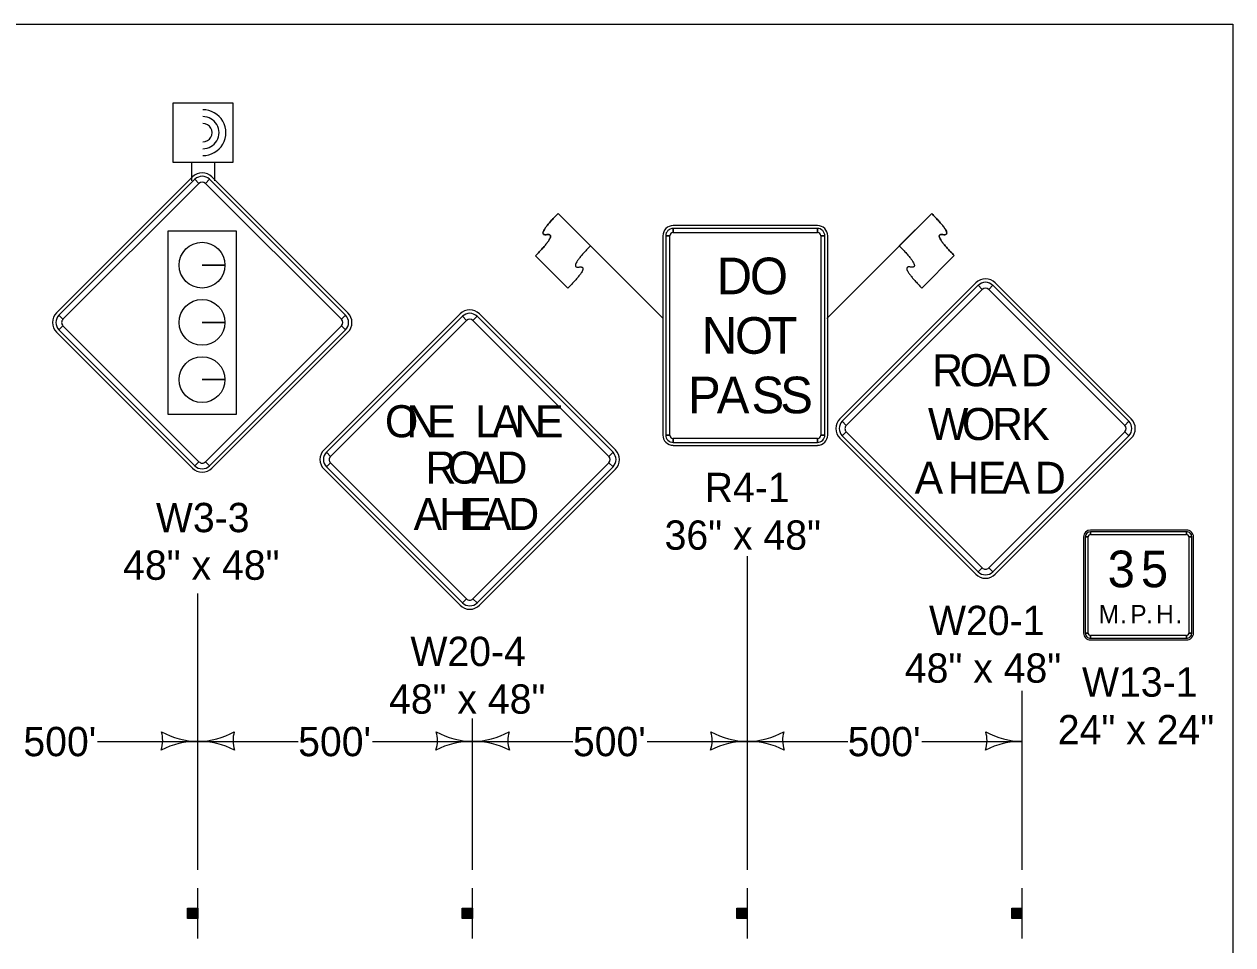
# Model space of a CAD drawing. Extents: x -2134934 to -2127057, y -2139046 to -2137036.
# Drawn here: x -2127757 to -2127097, y -2137539 to -2137036 of the extents above; entities that cross this region are included whole.
import ezdxf

# ---------------------------------------------------------------- set-up
doc = ezdxf.new("R2010")
doc.units = 0
for name, color, linetype in [('Barrier', 7, 'Continuous'), ('BridgeSuperStructureExisting', 7, 'Continuous'), ('Default', 7, 'Continuous'), ('TC_Barrier', 7, 'Continuous')]:
    doc.layers.add(name, color=color, linetype=linetype)

msp = doc.modelspace()

# ---------------------------------------------------------------- linework, layer by layer
at = {"layer": 'Barrier'}
for p, q in [((-2127664.88, -2137119.33), (-2127739.13, -2137193.57)), ((-2127663.56, -2137120.65), (-2127661.35, -2137122.86)), ((-2127657.81, -2137122.86), (-2127655.6, -2137120.65)), ((-2127580.03, -2137193.57), (-2127654.28, -2137119.33)), ((-2127407.97, -2137196.68), (-2127465.31, -2137139.38)), ((-2127465.31, -2137139.38), (-2127447.62, -2137157.06)), ((-2127318.68, -2137196.68), (-2127261.36, -2137139.36)), ((-2127261.36, -2137139.36), (-2127279.05, -2137157.04)), ((-2127323.73, -2137145.92), (-2127402.48, -2137145.92)), ((-2127402.48, -2137149.67), (-2127402.48, -2137147.48)), ((-2127323.73, -2137147.48), (-2127323.73, -2137149.67)), ((-2127408.11, -2137151.54), (-2127408.11, -2137260.29)), ((-2127406.54, -2137151.54), (-2127404.36, -2137151.54)), ((-2127321.86, -2137151.54), (-2127319.67, -2137151.54)), ((-2127318.11, -2137260.29), (-2127318.11, -2137151.54)), ((-2127460, -2137180.05), (-2127477.68, -2137162.37)), ((-2127266.66, -2137180.03), (-2127248.99, -2137162.35)), ((-2127647.17, -2137167.55), (-2127659.67, -2137167.55)), ((-2127659.67, -2137167.55), (-2127647.17, -2137167.55)), ((-2127237.26, -2137177.23), (-2127311.51, -2137251.47)), ((-2127152.41, -2137251.47), (-2127226.65, -2137177.23)), ((-2127235.93, -2137178.55), (-2127233.72, -2137180.76)), ((-2127230.19, -2137180.76), (-2127227.98, -2137178.55)), ((-2127735.59, -2137197.11), (-2127737.8, -2137194.9)), ((-2127518.85, -2137194.14), (-2127593.09, -2137268.39)), ((-2127581.36, -2137194.9), (-2127583.56, -2137197.11)), ((-2127517.52, -2137195.47), (-2127515.31, -2137197.68)), ((-2127511.78, -2137197.68), (-2127509.57, -2137195.47)), ((-2127433.99, -2137268.39), (-2127508.24, -2137194.14)), ((-2127739.13, -2137204.18), (-2127664.88, -2137278.43)), ((-2127737.8, -2137202.85), (-2127735.59, -2137200.64)), ((-2127647.17, -2137198.8), (-2127659.67, -2137198.8)), ((-2127659.67, -2137198.8), (-2127647.17, -2137198.8)), ((-2127654.28, -2137278.43), (-2127580.03, -2137204.18)), ((-2127583.56, -2137200.64), (-2127581.36, -2137202.85)), ((-2127647.17, -2137230.05), (-2127659.67, -2137230.05)), ((-2127659.67, -2137230.05), (-2127647.17, -2137230.05)), ((-2127307.97, -2137255.01), (-2127310.18, -2137252.8)), ((-2127153.73, -2137252.8), (-2127155.94, -2137255.01)), ((-2127404.36, -2137260.29), (-2127406.54, -2137260.29)), ((-2127402.48, -2137264.35), (-2127402.48, -2137262.17)), ((-2127323.73, -2137262.17), (-2127323.73, -2137264.35)), ((-2127319.67, -2137260.29), (-2127321.86, -2137260.29)), ((-2127311.51, -2137262.08), (-2127237.26, -2137336.33)), ((-2127310.18, -2137260.75), (-2127307.97, -2137258.54)), ((-2127226.65, -2137336.33), (-2127152.41, -2137262.08)), ((-2127155.94, -2137258.54), (-2127153.73, -2137260.75)), ((-2127589.56, -2137271.93), (-2127591.77, -2137269.72)), ((-2127435.32, -2137269.72), (-2127437.53, -2137271.93)), ((-2127402.48, -2137265.92), (-2127323.73, -2137265.92)), ((-2127661.35, -2137274.89), (-2127663.56, -2137277.1)), ((-2127655.6, -2137277.1), (-2127657.81, -2137274.89)), ((-2127591.77, -2137277.67), (-2127589.56, -2137275.46)), ((-2127437.53, -2137275.46), (-2127435.32, -2137277.67)), ((-2127593.09, -2137279), (-2127518.85, -2137353.24)), ((-2127508.24, -2137353.24), (-2127433.99, -2137279)), ((-2127178.44, -2137315.92), (-2127178.44, -2137368.42)), ((-2127177.5, -2137315.92), (-2127175.94, -2137315.92)), ((-2127122.19, -2137312.17), (-2127174.69, -2137312.17)), ((-2127174.69, -2137314.67), (-2127174.69, -2137313.1)), ((-2127122.19, -2137313.1), (-2127122.19, -2137314.67)), ((-2127120.94, -2137315.92), (-2127119.37, -2137315.92)), ((-2127118.44, -2137368.42), (-2127118.44, -2137315.92)), ((-2127233.72, -2137332.79), (-2127235.93, -2137335)), ((-2127227.98, -2137335), (-2127230.19, -2137332.79)), ((-2127515.31, -2137349.71), (-2127517.52, -2137351.92)), ((-2127509.57, -2137351.92), (-2127511.78, -2137349.71)), ((-2127175.94, -2137368.42), (-2127177.5, -2137368.42)), ((-2127119.37, -2137368.42), (-2127120.94, -2137368.42)), ((-2127174.69, -2137371.23), (-2127174.69, -2137369.67)), ((-2127174.69, -2137372.17), (-2127122.19, -2137372.17)), ((-2127122.19, -2137369.67), (-2127122.19, -2137371.23))]:
    msp.add_line(p, q, dxfattribs=at)
for points in [[(-2127663.56, -2137120.65), (-2127737.8, -2137194.9), (-2127735.59, -2137197.11), (-2127661.35, -2137122.86), (-2127663.56, -2137120.65)], [(-2127581.36, -2137194.9), (-2127655.6, -2137120.65), (-2127657.81, -2137122.86), (-2127583.56, -2137197.11), (-2127581.36, -2137194.9)], [(-2127640.85, -2137148.93), (-2127678.31, -2137148.93), (-2127678.31, -2137248.82), (-2127640.85, -2137248.82), (-2127640.85, -2137148.93)], [(-2127323.73, -2137147.48), (-2127402.48, -2137147.48), (-2127402.48, -2137149.67), (-2127323.73, -2137149.67), (-2127323.73, -2137147.48)], [(-2127406.54, -2137151.54), (-2127406.54, -2137260.29), (-2127404.36, -2137260.29), (-2127404.36, -2137151.54), (-2127406.54, -2137151.54)], [(-2127319.67, -2137260.29), (-2127319.67, -2137151.54), (-2127321.86, -2137151.54), (-2127321.86, -2137260.29), (-2127319.67, -2137260.29)], [(-2127235.93, -2137178.55), (-2127310.18, -2137252.8), (-2127307.97, -2137255.01), (-2127233.72, -2137180.76), (-2127235.93, -2137178.55)], [(-2127153.73, -2137252.8), (-2127227.98, -2137178.55), (-2127230.19, -2137180.76), (-2127155.94, -2137255.01), (-2127153.73, -2137252.8)], [(-2127517.52, -2137195.47), (-2127591.77, -2137269.72), (-2127589.56, -2137271.93), (-2127515.31, -2137197.68), (-2127517.52, -2137195.47)], [(-2127435.32, -2137269.72), (-2127509.57, -2137195.47), (-2127511.78, -2137197.68), (-2127437.53, -2137271.93), (-2127435.32, -2137269.72)], [(-2127737.8, -2137202.85), (-2127663.56, -2137277.1), (-2127661.35, -2137274.89), (-2127735.59, -2137200.64), (-2127737.8, -2137202.85)], [(-2127655.6, -2137277.1), (-2127581.36, -2137202.85), (-2127583.56, -2137200.64), (-2127657.81, -2137274.89), (-2127655.6, -2137277.1)], [(-2127402.48, -2137264.35), (-2127323.73, -2137264.35), (-2127323.73, -2137262.17), (-2127402.48, -2137262.17), (-2127402.48, -2137264.35)], [(-2127310.18, -2137260.75), (-2127235.93, -2137335), (-2127233.72, -2137332.79), (-2127307.97, -2137258.54), (-2127310.18, -2137260.75)], [(-2127227.98, -2137335), (-2127153.73, -2137260.75), (-2127155.94, -2137258.54), (-2127230.19, -2137332.79), (-2127227.98, -2137335)], [(-2127591.77, -2137277.67), (-2127517.52, -2137351.92), (-2127515.31, -2137349.71), (-2127589.56, -2137275.46), (-2127591.77, -2137277.67)], [(-2127509.57, -2137351.92), (-2127435.32, -2137277.67), (-2127437.53, -2137275.46), (-2127511.78, -2137349.71), (-2127509.57, -2137351.92)], [(-2127177.5, -2137315.92), (-2127177.5, -2137368.42), (-2127175.94, -2137368.42), (-2127175.94, -2137315.92), (-2127177.5, -2137315.92)], [(-2127122.19, -2137313.1), (-2127174.69, -2137313.1), (-2127174.69, -2137314.67), (-2127122.19, -2137314.67), (-2127122.19, -2137313.1)], [(-2127119.37, -2137368.42), (-2127119.37, -2137315.92), (-2127120.94, -2137315.92), (-2127120.94, -2137368.42), (-2127119.37, -2137368.42)], [(-2127174.69, -2137371.23), (-2127122.19, -2137371.23), (-2127122.19, -2137369.67), (-2127174.69, -2137369.67), (-2127174.69, -2137371.23)]]:
    msp.add_lwpolyline(points, close=True, dxfattribs=at)
for centre in [(-2127659.67, -2137167.55), (-2127659.67, -2137198.8), (-2127659.67, -2137230.05)]:
    msp.add_circle(centre, 12.5, dxfattribs=at)
for centre, radius, start, end in [((-2127659.58, -2137124.63), 7.5, 44.99999, 134.99974), ((-2127659.58, -2137124.63), 5.62, 44.99999, 134.99974), ((-2127659.58, -2137124.63), 2.5, 44.99999, 134.99974), ((-2127402.48, -2137151.54), 5.62, 90.00021, 179.99985), ((-2127402.48, -2137151.54), 4.06, 90.00021, 179.99985), ((-2127402.48, -2137151.54), 1.87, 90.00021, 179.99985), ((-2127323.73, -2137151.54), 5.62, 0, 90.00021), ((-2127323.73, -2137151.54), 4.06, 0, 90.00021), ((-2127323.73, -2137151.54), 1.87, 0, 90.00021), ((-2127231.96, -2137182.53), 7.5, 44.99999, 134.99974), ((-2127231.96, -2137182.53), 5.62, 44.99999, 134.99974), ((-2127231.96, -2137182.53), 2.5, 44.99999, 134.99974), ((-2127733.83, -2137198.88), 7.5, 134.99974, 224.99995), ((-2127733.83, -2137198.88), 5.62, 134.99974, 224.99995), ((-2127733.83, -2137198.88), 2.5, 134.99974, 224.99995), ((-2127585.33, -2137198.88), 2.5, 315.00016, 44.9998), ((-2127585.33, -2137198.88), 5.62, 315.00016, 44.9998), ((-2127585.33, -2137198.88), 7.5, 315.00016, 44.9998), ((-2127513.54, -2137199.45), 7.5, 44.99999, 134.99974), ((-2127513.54, -2137199.45), 5.62, 44.99999, 134.99974), ((-2127513.54, -2137199.45), 2.5, 44.99999, 134.99974), ((-2127306.2, -2137256.78), 7.5, 134.99974, 224.99995), ((-2127306.2, -2137256.78), 5.62, 134.99974, 224.99995), ((-2127306.2, -2137256.78), 2.5, 134.99974, 224.99995), ((-2127157.71, -2137256.78), 2.5, 315.00016, 44.9998), ((-2127157.71, -2137256.78), 5.62, 315.00016, 44.9998), ((-2127157.71, -2137256.78), 7.5, 315.00016, 44.9998), ((-2127402.48, -2137260.29), 5.62, 179.99985, 270.00006), ((-2127402.48, -2137260.29), 4.06, 179.99985, 270.00006), ((-2127402.48, -2137260.29), 1.87, 179.99985, 270.00006), ((-2127323.73, -2137260.29), 5.62, 270.00006, 0.00027), ((-2127323.73, -2137260.29), 4.06, 270.00006, 0.00027), ((-2127323.73, -2137260.29), 1.87, 270.00006, 0.00027), ((-2127587.79, -2137273.69), 7.5, 134.99974, 224.99995), ((-2127587.79, -2137273.69), 5.62, 134.99974, 224.99995), ((-2127439.3, -2137273.69), 5.62, 315.00016, 44.9998), ((-2127439.3, -2137273.69), 7.5, 315.00016, 44.9998), ((-2127659.58, -2137273.12), 2.5, 224.99995, 315.00016), ((-2127587.79, -2137273.69), 2.5, 134.99974, 224.99995), ((-2127439.3, -2137273.69), 2.5, 315.00016, 44.9998), ((-2127659.58, -2137273.12), 7.5, 224.99995, 315.00016), ((-2127659.58, -2137273.12), 5.62, 224.99995, 315.00016), ((-2127174.69, -2137315.92), 3.75, 90.00021, 179.99985), ((-2127174.69, -2137315.92), 2.81, 90.00021, 179.99985), ((-2127174.69, -2137315.92), 1.25, 90.00021, 179.99985), ((-2127122.19, -2137315.92), 3.75, 0, 90.00021), ((-2127122.19, -2137315.92), 2.81, 0, 90.00021), ((-2127122.19, -2137315.92), 1.25, 0, 90.00021), ((-2127231.96, -2137331.02), 5.62, 224.99995, 315.00016), ((-2127231.96, -2137331.02), 2.5, 224.99995, 315.00016), ((-2127231.96, -2137331.02), 7.5, 224.99995, 315.00016), ((-2127513.54, -2137347.94), 7.5, 224.99995, 315.00016), ((-2127513.54, -2137347.94), 5.62, 224.99995, 315.00016), ((-2127513.54, -2137347.94), 2.5, 224.99995, 315.00016), ((-2127174.69, -2137368.42), 3.75, 179.99985, 270.00006), ((-2127174.69, -2137368.42), 2.81, 179.99985, 270.00006), ((-2127174.69, -2137368.42), 1.25, 179.99985, 270.00006), ((-2127122.19, -2137368.42), 3.75, 270.00006, 0.00027), ((-2127122.19, -2137368.42), 2.81, 270.00006, 0.00027), ((-2127122.19, -2137368.42), 1.25, 270.00006, 0.00027)]:
    msp.add_arc(centre, radius, start, end, dxfattribs=at)
for points in [[(-2127477.68, -2137162.37), (-2127465.31, -2137149.99), (-2127477.68, -2137151.77), (-2127465.31, -2137139.38)], [(-2127248.99, -2137162.35), (-2127261.36, -2137149.98), (-2127248.99, -2137151.75), (-2127261.36, -2137139.36)], [(-2127447.62, -2137157.06), (-2127460, -2137169.44), (-2127447.63, -2137167.67), (-2127460, -2137180.05)], [(-2127279.05, -2137157.04), (-2127266.67, -2137169.43), (-2127279.04, -2137167.66), (-2127266.66, -2137180.03)]]:
    msp.add_open_spline(points, degree=2, dxfattribs=at)
at = {"layer": 'BridgeSuperStructureExisting'}
for p, q in [((-2127665.42, -2137111.41), (-2127665.42, -2137121.41)), ((-2127652.92, -2137111.41), (-2127652.92, -2137121.41)), ((-2127361.96, -2137497.66), (-2127361.96, -2137326.42)), ((-2127661.96, -2137497.66), (-2127661.96, -2137346.75)), ((-2127211.96, -2137497.66), (-2127211.96, -2137399.97)), ((-2127511.96, -2137497.66), (-2127511.96, -2137415.16)), ((-2127716.71, -2137427.66), (-2127661.96, -2137427.66)), ((-2127661.96, -2137427.66), (-2127607.21, -2137427.66)), ((-2127566.71, -2137427.66), (-2127511.96, -2137427.66)), ((-2127511.96, -2137427.66), (-2127457.21, -2137427.66)), ((-2127416.71, -2137427.66), (-2127361.96, -2137427.66)), ((-2127361.96, -2137427.66), (-2127307.21, -2137427.66)), ((-2127266.71, -2137427.66), (-2127211.96, -2137427.66)), ((-2127661.96, -2137535.16), (-2127661.96, -2137507.66)), ((-2127511.96, -2137535.16), (-2127511.96, -2137507.66)), ((-2127361.96, -2137535.16), (-2127361.96, -2137507.66)), ((-2127211.96, -2137535.16), (-2127211.96, -2137507.66)), ((-2127667.28, -2137524.3), (-2127667.28, -2137518.71)), ((-2127666.96, -2137518.71), (-2127666.96, -2137524.3)), ((-2127666.74, -2137524.3), (-2127666.74, -2137518.71)), ((-2127666.42, -2137518.71), (-2127666.42, -2137524.3)), ((-2127666.19, -2137524.3), (-2127666.21, -2137518.71)), ((-2127665.78, -2137518.71), (-2127665.76, -2137524.3)), ((-2127665.56, -2137524.3), (-2127665.56, -2137518.71)), ((-2127665.13, -2137518.71), (-2127665.13, -2137524.3)), ((-2127664.75, -2137524.3), (-2127664.75, -2137518.71)), ((-2127664.43, -2137518.71), (-2127664.41, -2137524.3)), ((-2127664.21, -2137524.3), (-2127664.21, -2137518.71)), ((-2127663.94, -2137518.71), (-2127663.94, -2137524.3)), ((-2127663.61, -2137524.3), (-2127663.61, -2137518.71)), ((-2127663.4, -2137518.71), (-2127663.4, -2137524.3)), ((-2127663.18, -2137524.3), (-2127663.18, -2137518.71)), ((-2127662.91, -2137518.71), (-2127662.91, -2137524.3)), ((-2127662.65, -2137524.3), (-2127662.65, -2137518.71)), ((-2127662.37, -2137518.71), (-2127662.37, -2137524.3)), ((-2127517.28, -2137524.3), (-2127517.28, -2137518.71)), ((-2127516.96, -2137518.71), (-2127516.96, -2137524.3)), ((-2127516.74, -2137524.3), (-2127516.74, -2137518.71)), ((-2127516.42, -2137518.71), (-2127516.42, -2137524.3)), ((-2127516.19, -2137524.3), (-2127516.21, -2137518.71)), ((-2127515.78, -2137518.71), (-2127515.76, -2137524.3)), ((-2127515.56, -2137524.3), (-2127515.56, -2137518.71)), ((-2127515.13, -2137518.71), (-2127515.13, -2137524.3)), ((-2127514.75, -2137524.3), (-2127514.75, -2137518.71)), ((-2127514.43, -2137518.71), (-2127514.41, -2137524.3)), ((-2127514.21, -2137524.3), (-2127514.21, -2137518.71)), ((-2127513.94, -2137518.71), (-2127513.94, -2137524.3)), ((-2127513.61, -2137524.3), (-2127513.61, -2137518.71)), ((-2127513.4, -2137518.71), (-2127513.4, -2137524.3)), ((-2127513.18, -2137524.3), (-2127513.18, -2137518.71)), ((-2127512.91, -2137518.71), (-2127512.91, -2137524.3)), ((-2127512.65, -2137524.3), (-2127512.65, -2137518.71)), ((-2127512.37, -2137518.71), (-2127512.37, -2137524.3)), ((-2127367.28, -2137524.3), (-2127367.28, -2137518.71)), ((-2127366.96, -2137518.71), (-2127366.96, -2137524.3)), ((-2127366.74, -2137524.3), (-2127366.74, -2137518.71)), ((-2127366.42, -2137518.71), (-2127366.42, -2137524.3)), ((-2127366.19, -2137524.3), (-2127366.21, -2137518.71)), ((-2127365.78, -2137518.71), (-2127365.76, -2137524.3)), ((-2127365.56, -2137524.3), (-2127365.56, -2137518.71)), ((-2127365.13, -2137518.71), (-2127365.13, -2137524.3)), ((-2127364.75, -2137524.3), (-2127364.75, -2137518.71)), ((-2127364.43, -2137518.71), (-2127364.41, -2137524.3)), ((-2127364.21, -2137524.3), (-2127364.21, -2137518.71)), ((-2127363.94, -2137518.71), (-2127363.94, -2137524.3)), ((-2127363.61, -2137524.3), (-2127363.61, -2137518.71)), ((-2127363.4, -2137518.71), (-2127363.4, -2137524.3)), ((-2127363.18, -2137524.3), (-2127363.18, -2137518.71)), ((-2127362.91, -2137518.71), (-2127362.91, -2137524.3)), ((-2127362.65, -2137524.3), (-2127362.65, -2137518.71)), ((-2127362.37, -2137518.71), (-2127362.37, -2137524.3)), ((-2127217.28, -2137524.3), (-2127217.28, -2137518.71)), ((-2127216.96, -2137518.71), (-2127216.96, -2137524.3)), ((-2127216.74, -2137524.3), (-2127216.74, -2137518.71)), ((-2127216.42, -2137518.71), (-2127216.42, -2137524.3)), ((-2127216.2, -2137524.3), (-2127216.21, -2137518.71)), ((-2127215.78, -2137518.71), (-2127215.76, -2137524.3)), ((-2127215.56, -2137524.3), (-2127215.56, -2137518.71)), ((-2127215.13, -2137518.71), (-2127215.13, -2137524.3)), ((-2127214.75, -2137524.3), (-2127214.75, -2137518.71)), ((-2127214.43, -2137518.71), (-2127214.41, -2137524.3)), ((-2127214.21, -2137524.3), (-2127214.21, -2137518.71)), ((-2127213.94, -2137518.71), (-2127213.94, -2137524.3)), ((-2127213.61, -2137524.3), (-2127213.61, -2137518.71)), ((-2127213.4, -2137518.71), (-2127213.4, -2137524.3)), ((-2127213.18, -2137524.3), (-2127213.18, -2137518.71)), ((-2127212.91, -2137518.71), (-2127212.91, -2137524.3)), ((-2127212.65, -2137524.3), (-2127212.65, -2137518.71)), ((-2127212.37, -2137518.71), (-2127212.37, -2137524.3))]:
    msp.add_line(p, q, dxfattribs=at)
for points in [[(-2127675.42, -2137111.41), (-2127675.42, -2137078.91), (-2127642.92, -2137078.91), (-2127642.92, -2137111.41)], [(-2127662.05, -2137518.71), (-2127662.05, -2137524.34), (-2127667.68, -2137524.34), (-2127667.68, -2137518.71)], [(-2127512.05, -2137518.71), (-2127512.05, -2137524.34), (-2127517.68, -2137524.34), (-2127517.68, -2137518.71)], [(-2127362.05, -2137518.71), (-2127362.05, -2137524.34), (-2127367.68, -2137524.34), (-2127367.68, -2137518.71)], [(-2127212.05, -2137518.71), (-2127212.05, -2137524.34), (-2127217.68, -2137524.34), (-2127217.68, -2137518.71)]]:
    msp.add_lwpolyline(points, close=True, dxfattribs=at)
for centre, radius, start, end in [((-2127659.16, -2137095.18), 12.5, 269.40414, 90.54446), ((-2127659.16, -2137095.18), 12.5, 269.40414, 90.54446), ((-2127659.16, -2137095.18), 8.75, 269.40414, 90.54446), ((-2127659.16, -2137095.18), 5, 269.40414, 90.54446), ((-2127697.57, -2137427.04), 16.42, 341.26665, 16.73335), ((-2127662.68, -2137470.15), 42.5, 89.0176, 117.07249), ((-2127661.2, -2137385.17), 42.5, 240.92751, 268.9824), ((-2127662.71, -2137385.17), 42.5, 271.0176, 299.07249), ((-2127661.23, -2137470.15), 42.5, 62.92751, 90.9824), ((-2127626.34, -2137427.04), 16.42, 163.26665, 198.73335), ((-2127547.57, -2137427.04), 16.42, 341.26665, 16.73335), ((-2127512.68, -2137470.15), 42.5, 89.0176, 117.07249), ((-2127511.2, -2137385.17), 42.5, 240.92751, 268.9824), ((-2127512.71, -2137385.17), 42.5, 271.0176, 299.07249), ((-2127511.23, -2137470.15), 42.5, 62.92751, 90.9824), ((-2127476.34, -2137427.04), 16.42, 163.26665, 198.73335), ((-2127397.57, -2137427.04), 16.42, 341.26665, 16.73335), ((-2127362.68, -2137470.15), 42.5, 89.0176, 117.07249), ((-2127361.2, -2137385.17), 42.5, 240.92751, 268.9824), ((-2127362.71, -2137385.17), 42.5, 271.0176, 299.07249), ((-2127361.23, -2137470.15), 42.5, 62.92751, 90.9824), ((-2127326.34, -2137427.04), 16.42, 163.26665, 198.73335), ((-2127247.57, -2137427.04), 16.42, 341.26665, 16.73335), ((-2127212.68, -2137470.15), 42.5, 89.0176, 117.07249), ((-2127211.2, -2137385.17), 42.5, 240.92751, 268.9824)]:
    msp.add_arc(centre, radius, start, end, dxfattribs=at)
at = {"layer": 'Default'}
msp.add_lwpolyline([(-2130231.95, -2137035.95), (-2127096.96, -2137035.95), (-2127096.96, -2139045.94), (-2130231.95, -2139045.94)], close=True, dxfattribs=at)
at = {"layer": 'TC_Barrier'}
for p, q in [((-2127477.68, -2137162.37), (-2127460, -2137180.05)), ((-2127248.99, -2137162.35), (-2127266.66, -2137180.03))]:
    msp.add_line(p, q, dxfattribs=at)
for points in [[(-2127465.31, -2137139.38), (-2127477.68, -2137151.77), (-2127465.31, -2137149.99), (-2127477.68, -2137162.37)], [(-2127261.36, -2137139.36), (-2127248.99, -2137151.75), (-2127261.36, -2137149.98), (-2127248.99, -2137162.35)], [(-2127447.62, -2137157.06), (-2127460, -2137169.44), (-2127447.63, -2137167.67), (-2127460, -2137180.05)], [(-2127279.05, -2137157.04), (-2127266.67, -2137169.43), (-2127279.04, -2137167.66), (-2127266.66, -2137180.03)]]:
    msp.add_open_spline(points, degree=2, dxfattribs=at)

# ---------------------------------------------------------------- texts
at = {"layer": 'Barrier'}
for s, height, p in [('D', 20, (-2127378.73, -2137183.42)), ('O', 20, (-2127360.61, -2137183.42)), ('N', 20, (-2127386.86, -2137215.92)), ('O', 20, (-2127368.73, -2137215.92)), ('T', 20, (-2127350.92, -2137215.92)), ('R', 17.5, (-2127261.12, -2137233.65)), ('O', 17.5, (-2127246.11, -2137233.65)), ('A', 17.5, (-2127230.56, -2137233.65)), ('D', 17.5, (-2127212.68, -2137233.65)), ('P', 20, (-2127394.37, -2137248.42)), ('A', 20, (-2127378.69, -2137248.42)), ('S', 20, (-2127359.72, -2137248.42)), ('S', 20, (-2127344.03, -2137248.42)), ('O', 17.5, (-2127559.83, -2137261.51)), ('N', 17.5, (-2127548.05, -2137261.51)), ('E', 17.5, (-2127536.83, -2137261.51)), ('L', 17.5, (-2127510.58, -2137261.51)), ('A', 17.5, (-2127501.38, -2137261.51)), ('N', 17.5, (-2127489.11, -2137261.51)), ('E', 17.5, (-2127477.88, -2137261.51)), ('W', 17.5, (-2127263.4, -2137263.03)), ('O', 17.5, (-2127244.81, -2137263.03)), ('R', 17.5, (-2127228.4, -2137263.03)), ('K', 17.5, (-2127212.54, -2137263.03)), ('R', 17.5, (-2127537.72, -2137286.82)), ('O', 17.5, (-2127525.43, -2137286.82)), ('A', 17.5, (-2127512.59, -2137286.82)), ('D', 17.5, (-2127498.94, -2137286.82)), ('A', 17.5, (-2127270.68, -2137292.4)), ('H', 17.5, (-2127252.47, -2137292.4)), ('E', 17.5, (-2127236.24, -2137292.4)), ('A', 17.5, (-2127223.2, -2137292.4)), ('D', 17.5, (-2127204.99, -2137292.4)), ('R4-1', 16, (-2127385.27, -2137296.92)), ('A', 17.5, (-2127544.16, -2137312.13)), ('H', 17.5, (-2127530.29, -2137312.13)), ('E', 17.5, (-2127517.08, -2137312.13)), ('A', 17.5, (-2127506.36, -2137312.13)), ('D', 17.5, (-2127492.5, -2137312.13)), ('W3-3', 16, (-2127684.87, -2137313.34)), ('36" x 48"', 16, (-2127407.17, -2137322.92)), ('48" x 48"', 16, (-2127702.75, -2137339.34)), ('3', 20, (-2127165.29, -2137343.41)), ('5', 20, (-2127147.16, -2137343.41)), ('W20-1', 16, (-2127262.81, -2137369.52)), ('M', 10, (-2127170.21, -2137363.1)), ('P', 10, (-2127152.96, -2137363.1)), ('H', 10, (-2127138.84, -2137363.1)), ('.', 10, (-2127158.42, -2137363.1)), ('.', 10, (-2127144.3, -2137363.1)), ('.', 10, (-2127128.37, -2137363.1)), ('W20-4', 16, (-2127545.91, -2137386.44)), ('48" x 48"', 16, (-2127276.02, -2137395.52)), ('W13-1', 16, (-2127179.29, -2137403.17)), ('48" x 48"', 16, (-2127557.61, -2137412.44)), ('24" x 24"', 16, (-2127192.5, -2137429.17))]:
    msp.add_text(s, height=height, dxfattribs=at).set_placement(p)
at = {"layer": 'BridgeSuperStructureExisting'}
for p in [(-2127757.21, -2137435.66), (-2127607.21, -2137435.66), (-2127457.21, -2137435.66), (-2127307.21, -2137435.66)]:
    msp.add_text("500'", height=16, dxfattribs=at).set_placement(p)

doc.saveas('drawing.dxf')
